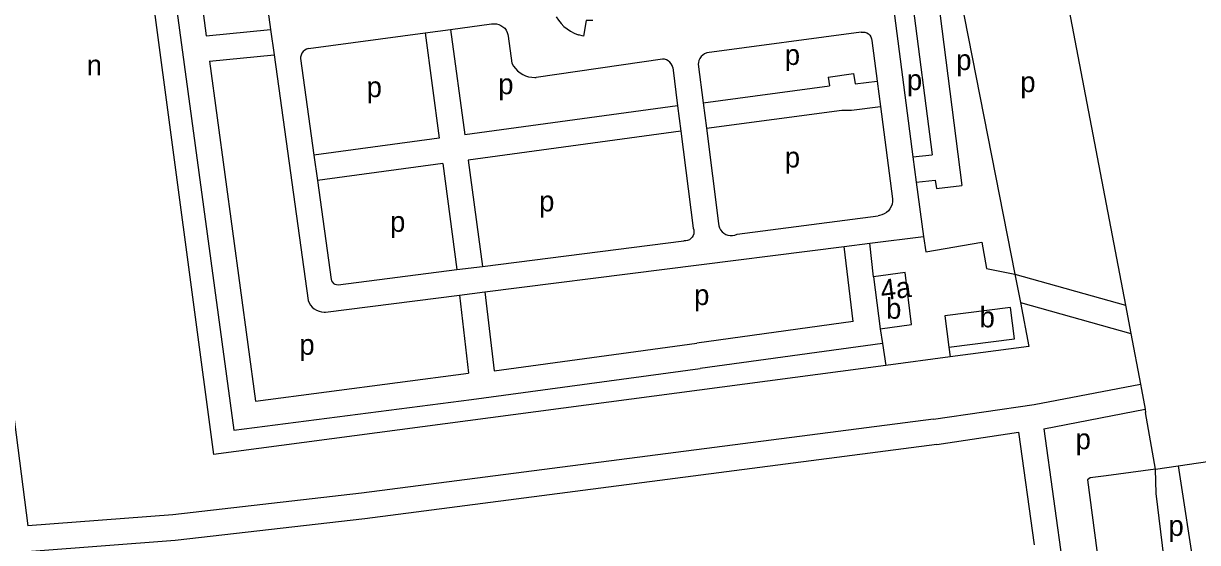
# Model space of a CAD drawing. Extents: x 161093 to 163177, y 379000 to 380904.
# Drawn here: x 162389.1 to 162617.8, y 379873.5 to 379974.6 of the extents above; entities that cross this region are included whole.
import ezdxf

# ---------------------------------------------------------------- set-up
doc = ezdxf.new("R2010")
doc.units = 0
for name, color, linetype in [('BLT_Basislijn', 7, 'Continuous'), ('BLT_Bebouwing', 7, 'Continuous'), ('BLT_Centroide', 7, 'Continuous'), ('BLT_Huisnummer', 7, 'Continuous')]:
    doc.layers.add(name, color=color, linetype=linetype)

msp = doc.modelspace()

# ---------------------------------------------------------------- linework, layer by layer
at = {"layer": 'BLT_Basislijn'}
for p, q in [((162393.61, 380133.91), (162426.07, 379890.63)), ((162429.85, 380026.4), (162437.2, 379973.41)), ((162418.54, 380017.49), (162424.67, 379972.19)), ((162566.32, 380006.89), (162582.22, 379925.74)), ((162566.17, 379987.69), (162571.89, 379943.06)), ((162562.02, 379980.67), (162566.09, 379949.01)), ((162558.23, 379980.21), (162562.37, 379948.61)), ((162472.28, 379973.41), (162480.28, 379974.48)), ((162424.67, 379972.19), (162437.2, 379973.41)), ((162437.2, 379973.41), (162437.89, 379968.45)), ((162444.61, 379969.73), (162467.33, 379972.75)), ((162467.33, 379972.75), (162472.28, 379973.41)), ((162467.33, 379972.75), (162470.08, 379952.25)), ((162472.28, 379973.41), (162475.03, 379952.92)), ((162483.52, 379972.08), (162484.23, 379966.82)), ((162552.27, 379972.88), (162522.18, 379968.84)), ((162554.35, 379971.27), (162555.39, 379963.34)), ((162425.34, 379967.23), (162437.89, 379968.45)), ((162437.89, 379968.45), (162444.52, 379920.64)), ((162443.03, 379967.73), (162445.64, 379948.94)), ((162513.54, 379967.63), (162488.98, 379964.09)), ((162520.53, 379966.63), (162521.48, 379959.14)), ((162515.57, 379966), (162516.52, 379958.55)), ((162545.86, 379964.1), (162550.8, 379964.84)), ((162550.8, 379964.84), (162551.1, 379962.85)), ((162521.48, 379959.14), (162546.1, 379962.46)), ((162545.86, 379964.1), (162546.1, 379962.46)), ((162551.1, 379962.85), (162555.39, 379963.34)), ((162555.39, 379963.34), (162556.04, 379958.38)), ((162516.52, 379958.55), (162475.03, 379952.92)), ((162516.52, 379958.55), (162517.15, 379953.59)), ((162521.48, 379959.14), (162522.11, 379954.18)), ((162556.04, 379958.38), (162558.4, 379940.41)), ((162517.15, 379953.59), (162475.69, 379947.97)), ((162517.15, 379953.59), (162519.54, 379934.75)), ((162522.11, 379954.18), (162524.47, 379935.63)), ((162470.08, 379952.25), (162445.64, 379948.94)), ((162445.64, 379948.94), (162446.33, 379943.99)), ((162562.37, 379948.61), (162566.09, 379949.01)), ((162562.37, 379948.61), (162563.02, 379943.65)), ((162470.74, 379947.3), (162446.33, 379943.99)), ((162470.74, 379947.3), (162473.51, 379926.65)), ((162475.69, 379947.97), (162478.47, 379927.28)), ((162446.33, 379943.99), (162449.02, 379924.74)), ((162563.02, 379943.65), (162566.72, 379944.05)), ((162566.72, 379944.05), (162566.93, 379942.43)), ((162563.02, 379943.65), (162564.4, 379933.1)), ((162566.93, 379942.43), (162571.89, 379943.06)), ((162528.11, 379933.55), (162555.6, 379937.12)), ((162553.95, 379931.78), (162564.4, 379933.1)), ((162478.47, 379927.28), (162517.71, 379932.24)), ((162478.96, 379922.3), (162548.99, 379931.15)), ((162548.99, 379931.15), (162553.95, 379931.78)), ((162550.74, 379916.53), (162548.99, 379931.15)), ((162554.71, 379925.25), (162553.95, 379931.78)), ((162383.58, 379925.9), (162389.92, 379876.74)), ((162450.37, 379923.72), (162473.51, 379926.65)), ((162473.51, 379926.65), (162478.47, 379927.28)), ((162582.22, 379925.74), (162583.29, 379920.24)), ((162582.22, 379925.74), (162603.75, 379919.71)), ((162447.9, 379918.37), (162474, 379921.67)), ((162474, 379921.67), (162478.96, 379922.3)), ((162474, 379921.67), (162475.77, 379906.52)), ((162583.29, 379920.24), (162604.8, 379914.22)), ((162583.29, 379920.24), (162584.96, 379911.71)), ((162603.75, 379919.71), (162604.8, 379914.22)), ((162550.74, 379916.53), (162520.23, 379912.36)), ((162555.98, 379915.15), (162556.46, 379912.26)), ((162604.8, 379914.22), (162606.68, 379904.37)), ((162556.46, 379912.26), (162520.91, 379907.41)), ((162556.46, 379912.26), (162557.05, 379908.01)), ((162584.96, 379911.71), (162569.59, 379909.67)), ((162569.59, 379909.67), (162557.05, 379908.01)), ((162569.37, 379911.55), (162569.59, 379909.67)), ((162557.05, 379908.01), (162426.07, 379890.63)), ((162476.37, 379901.36), (162520.91, 379907.41)), ((162606.68, 379904.37), (162606.88, 379903.33)), ((162606.88, 379903.33), (162607.58, 379899.46)), ((162587.86, 379895.67), (162607.58, 379899.46)), ((162607.58, 379899.46), (162607.69, 379898.82)), ((162609.63, 379887.8), (162607.69, 379898.82)), ((162567.03, 379892.57), (162582.9, 379894.99)), ((162582.9, 379894.99), (162585.96, 379873.07)), ((162587.86, 379895.67), (162596.45, 379834.05)), ((162609.63, 379887.8), (162614.03, 379888.46))]:
    msp.add_line(p, q, dxfattribs=at)
for points in [[(162413.58, 380016.82), (162430.02, 379895.42), (162476.37, 379901.36)], [(162566.32, 380006.89), (162571, 380007.59), (162579.61, 380009.3), (162584.07, 380008.64), (162586.19, 380006.73), (162587.57, 380004.53), (162600, 379939.37), (162603.75, 379919.71)], [(162480.28, 379974.48), (162480.74, 379974.53), (162481.21, 379974.5), (162481.66, 379974.39), (162482.09, 379974.21), (162482.48, 379973.95), (162482.82, 379973.64), (162483.11, 379973.27), (162483.32, 379972.85), (162483.46, 379972.41), (162483.52, 379972.08)], [(162552.27, 379972.88), (162552.64, 379972.91), (162553.01, 379972.86), (162553.37, 379972.73), (162553.68, 379972.53), (162553.95, 379972.27), (162554.16, 379971.95), (162554.29, 379971.6), (162554.35, 379971.27)], [(162444.61, 379969.73), (162444.22, 379969.59), (162443.87, 379969.38), (162443.57, 379969.1), (162443.33, 379968.77), (162443.15, 379968.4), (162443.05, 379968), (162443.03, 379967.73)], [(162425.34, 379967.23), (162434.3, 379901.03), (162475.77, 379906.52)], [(162484.23, 379966.82), (162484.53, 379966.28), (162484.9, 379965.78), (162485.32, 379965.33), (162485.81, 379964.94), (162486.34, 379964.62), (162486.9, 379964.37), (162487.49, 379964.19), (162488.1, 379964.1), (162488.72, 379964.08), (162488.98, 379964.09)], [(162515.57, 379966), (162515.46, 379966.39), (162515.26, 379966.74), (162515.01, 379967.05), (162514.69, 379967.3), (162514.33, 379967.49), (162513.95, 379967.6), (162513.54, 379967.63)], [(162522.18, 379968.84), (162521.78, 379968.67), (162521.42, 379968.43), (162521.11, 379968.13), (162520.86, 379967.78), (162520.67, 379967.39), (162520.56, 379966.97), (162520.53, 379966.63)], [(162614.03, 379888.46), (162624.15, 379889.96), (162624.6, 379965.05)], [(162522.11, 379954.18), (162548.49, 379957.73), (162550.38, 379957.73), (162556.04, 379958.38)], [(162558.4, 379940.41), (162558.39, 379939.91), (162558.29, 379939.41), (162558.12, 379938.94), (162557.88, 379938.5), (162557.57, 379938.11), (162557.2, 379937.77), (162556.78, 379937.49), (162556.32, 379937.29), (162555.84, 379937.16), (162555.6, 379937.12)], [(162519.54, 379934.75), (162519.66, 379934.4), (162519.7, 379934.02), (162519.66, 379933.65), (162519.55, 379933.29), (162519.36, 379932.96), (162519.11, 379932.68), (162518.8, 379932.46), (162518.46, 379932.31), (162518.09, 379932.23), (162517.71, 379932.24)], [(162524.47, 379935.63), (162524.53, 379935.19), (162524.67, 379934.77), (162524.89, 379934.38), (162525.17, 379934.03), (162525.51, 379933.74), (162525.89, 379933.51), (162526.31, 379933.36), (162526.75, 379933.28), (162527.2, 379933.28), (162527.63, 379933.36), (162528.11, 379933.55)], [(162564.4, 379933.1), (162564.85, 379930.13), (162575.76, 379932.02), (162576.68, 379926.85), (162582.22, 379925.74)], [(162449.02, 379924.74), (162449.1, 379924.44), (162449.27, 379924.18), (162449.49, 379923.96), (162449.76, 379923.8), (162450.06, 379923.73), (162450.37, 379923.72)], [(162478.96, 379922.3), (162480.75, 379906.97), (162520.23, 379912.36)], [(162444.52, 379920.64), (162444.73, 379920.17), (162445, 379919.73), (162445.34, 379919.34), (162445.73, 379919), (162446.17, 379918.73), (162446.65, 379918.53), (162447.15, 379918.41), (162447.66, 379918.36), (162447.9, 379918.37)], [(162566.39, 379897.53), (162585.96, 379900.4), (162606.68, 379904.37)], [(162566.39, 379897.53), (162454.95, 379883.12), (162418.15, 379878.88), (162389.92, 379876.74)], [(162567.03, 379892.57), (162455.56, 379878.15), (162418.63, 379873.91), (162390.62, 379871.78)], [(162609.63, 379887.8), (162600, 379886.52), (162596.87, 379886.1), (162596.36, 379885.75), (162600, 379858.18), (162600.03, 379857.96)], [(162611.88, 379865.46), (162609.78, 379883.07), (162609.63, 379887.8)], [(162614.03, 379888.46), (162617.34, 379866.91), (162617.44, 379866.25)]]:
    msp.add_lwpolyline(points, dxfattribs=at)
at = {"layer": 'BLT_Bebouwing'}
for p, q in [((162560.83, 379926.06), (162554.71, 379925.25)), ((162562.1, 379915.96), (162560.83, 379926.06)), ((162554.71, 379925.25), (162555.98, 379915.15)), ((162555.98, 379915.15), (162562.1, 379915.96))]:
    msp.add_line(p, q, dxfattribs=at)
for points in [[(162492.85, 379975.89), (162493.29, 379975.22), (162493.8, 379974.59), (162494.37, 379974.02), (162495, 379973.51), (162495.67, 379973.06), (162496.38, 379972.68), (162497.13, 379972.37), (162497.22, 379972.34)], [(162500, 379975.16), (162498.68, 379975.18), (162498.15, 379972.12), (162497.22, 379972.34)], [(162581.34, 379919.27), (162568.59, 379917.63), (162569.37, 379911.55)], [(162569.37, 379911.55), (162582.12, 379913.19), (162581.34, 379919.27)]]:
    msp.add_lwpolyline(points, dxfattribs=at)

# ---------------------------------------------------------------- texts
at = {"layer": 'BLT_Centroide'}
for s, p in [('p', (162537.4, 379966.5)), ('n', (162401.38, 379964.45)), ('p', (162570.8, 379965.5)), ('p', (162561.19, 379961.61)), ('p', (162583.28, 379961.2)), ('p', (162455.93, 379960.23)), ('p', (162481.57, 379960.8)), ('p', (162537.4, 379946.54)), ('p', (162489.54, 379937.99)), ('p', (162460.49, 379934)), ('p', (162519.74, 379919.75)), ('b', (162557.14, 379917.08)), ('b', (162575.35, 379915.41)), ('p', (162442.82, 379910.06)), ('p', (162594.06, 379891.68)), ('p', (162612.16, 379874.8))]:
    msp.add_text(s, height=4, dxfattribs=at).set_placement(p)
at = {"layer": 'BLT_Huisnummer'}
msp.add_text('4a', height=4, rotation=6.9465, dxfattribs=at).set_placement((162556.29, 379920.64))

doc.saveas('drawing.dxf')
